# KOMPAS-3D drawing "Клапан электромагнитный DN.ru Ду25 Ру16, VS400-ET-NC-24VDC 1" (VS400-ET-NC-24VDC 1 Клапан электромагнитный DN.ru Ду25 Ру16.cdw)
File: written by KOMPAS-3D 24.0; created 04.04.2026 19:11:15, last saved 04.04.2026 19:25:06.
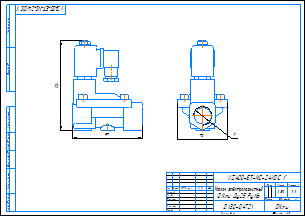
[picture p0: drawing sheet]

Document properties: c3d_UniqueCompID: ef56311e-7521-43dc-8291-0e6108b3d81d; Обозначение: VS400-ET-NC-220VAC 1; Наименование: Клапан электромагнитный DN.ru Ду25 Ру16; Автор: artio; Класс точности: c; Знак неуказанной шероховатости: Шероховатость не задана; Рассекать на разрезах: Да; c3d_UniqueCompID: ef56311e-7521-43dc-8291-0e6108b3d81d; Обозначение: VS400-ET-NC-220VAC 1-2; Наименование: Клапан электромагнитный DN.ru Ду15 Ру16; Автор: artio; Класс точности: c; Знак неуказанной шероховатости: Шероховатость не задана; Рассекать на разрезах: Да; c3d_UniqueCompID: ef56311e-7521-43dc-8291-0e6108b3d81d; Обозначение: VS400-ET-NC-220VAC 3-4; Наименование: Клапан электромагнитный DN.ru Ду20 Ру16; Автор: artio; Класс точности: c; Знак неуказанной шероховатости: Шероховатость не задана; Рассекать на разрезах: Да; c3d_UniqueCompID: ef56311e-7521-43dc-8291-0e6108b3d81d; Обозначение: VS400-ET-NC-220VAC 3-8; Наименование: Клапан электромагнитный DN.ru Ду10 Ру16; Автор: artio; Класс точности: c; Знак неуказанной шероховатости: Шероховатость не задана; Рассекать на разрезах: Да; Автор: artio; Форматы листов документа: A3; Полное имя файла: VS400-ET-NC-24VDC 1 Клапан электромагнитный DN.ru Ду25 Ру16.m3d; Масса: 1.524; Наименование: Клапан электромагнитный DN.ru Ду25 Ру16; Количество листов документа: 1; Примечание: D130-04721

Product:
- Body: Тело 1  | qty 1
    Масса: 1.76797
- Part/product: Клапан электромагнитный DN.ru Ду25 Ру16  | designation VS400-ET-NC-24VDC 1
    Масса: 1.524
    Раздел спецификации: Прочие изделия
    Примечание: D130-04721
    additional columns: ef56311e-7521-43dc-8291-0e6108b3d81d; VS400-ET-NC-220VAC 1; artio; c; Шероховатость не задана; Да

Views: Вид 1, Спереди
Referenced files in C:\Users\artio\OneDrive\Рабочий стол\Клапан электромагнитный DN.ru\VS400-ET-NC\VS400-ET-NC-24VDC\: VS400-ET-NC-24VDC 3-8 Клапан электромагнитный DN.ru Ду10 Ру16.m3d, VS400-ET-NC-24VDC 1 Клапан электромагнитный DN.ru Ду25 Ру16.m3d
Referenced files in C:\Users\artio\OneDrive\Рабочий стол\Клапан электромагнитный DN.ru\VS400-ET-NC\: VS400-ET-NC-24VDC 3-8 Клапан электромагнитный DN.ru Ду10 Ру16.cdw
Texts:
  VS400-ET-NC-24VDC 1
  Клапан электромагнитный
  DN.ru Ду25 Ру16
  VS400-ET-NC-24VDC 1"
  VS400-ET-NC-24VDC 1"-
  Клапан электромагнитный DN.ru Ду25 Ру16
  VS400-ET-NC-24VDC 1 Клапан электромагнитный DN.ru Ду25 Ру16
Dimensions and other numbers on the sheet: 0; 3; 2; 4; 70; 1:1; 1; 1,52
